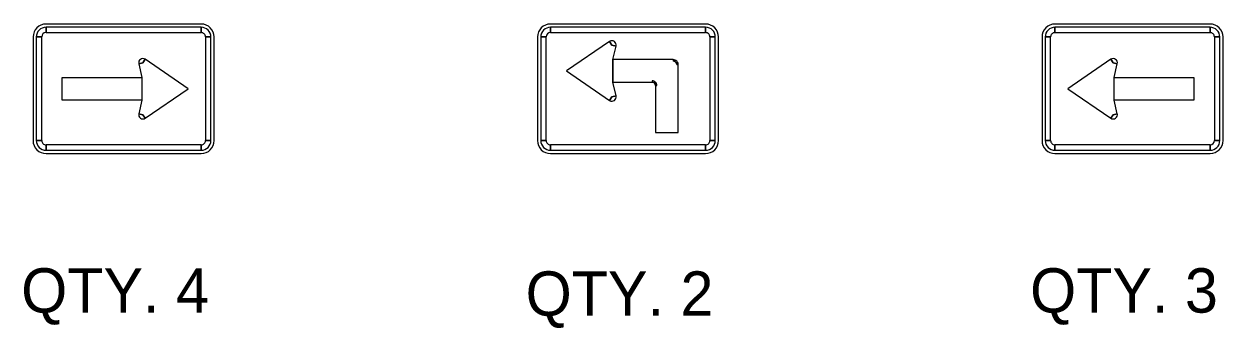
# Model space of a CAD drawing. Extents: x 10133 to 81668, y 5524 to 11018.
# Drawn here: x 25973 to 26582, y 9278 to 9432 of the extents above; entities that cross this region are included whole.
import ezdxf

# ---------------------------------------------------------------- set-up
doc = ezdxf.new("R2010")
doc.units = 0
doc.layers.add('DisCLMLSUR', color=7, linetype='Continuous')
doc.layers.add('Level 6', color=7, linetype='Continuous')

msp = doc.modelspace()

# ---------------------------------------------------------------- linework, layer by layer
at = {"layer": 'Level 6'}
for p, q in [((26063.35, 9432.44), (25984.61, 9432.44)), ((26319.35, 9432.44), (26240.61, 9432.44)), ((26575.35, 9432.44), (26496.61, 9432.44)), ((25978.05, 9425.87), (25978.05, 9373.38)), ((25979.69, 9425.87), (25982.42, 9425.87)), ((25984.61, 9428.06), (25984.61, 9430.77)), ((26063.35, 9430.77), (26063.35, 9428.06)), ((26065.54, 9425.87), (26068.27, 9425.87)), ((26069.91, 9373.38), (26069.91, 9425.87)), ((26234.05, 9425.87), (26234.05, 9373.38)), ((26235.69, 9425.87), (26238.42, 9425.87)), ((26240.61, 9428.06), (26240.61, 9430.77)), ((26319.35, 9430.77), (26319.35, 9428.06)), ((26321.54, 9425.87), (26324.27, 9425.87)), ((26325.91, 9373.38), (26325.91, 9425.87)), ((26490.05, 9425.87), (26490.05, 9373.38)), ((26491.69, 9425.87), (26494.42, 9425.87)), ((26496.61, 9428.06), (26496.61, 9430.77)), ((26575.35, 9430.77), (26575.35, 9428.06)), ((26577.54, 9425.87), (26580.27, 9425.87)), ((26581.91, 9373.38), (26581.91, 9425.87)), ((26270.61, 9423.64), (26271.78, 9421.76)), ((26271.78, 9421.76), (26273.91, 9421.28)), ((26033.82, 9412.75), (26034.99, 9414.59)), ((26302.94, 9414.41), (26302.94, 9413.67)), ((26524.97, 9414.59), (26526.14, 9412.75)), ((26031.69, 9412.27), (26033.82, 9412.75)), ((26304.69, 9411.92), (26305.41, 9411.92)), ((26526.14, 9412.75), (26528.27, 9412.27)), ((26292.28, 9403.61), (26292.28, 9402.91)), ((26293.92, 9401.29), (26294.6, 9401.29)), ((26271.78, 9395.51), (26270.61, 9393.68)), ((26273.91, 9396.04), (26271.78, 9395.51)), ((26033.82, 9386.5), (26031.69, 9386.98)), ((26034.99, 9384.66), (26033.82, 9386.5)), ((26526.14, 9386.5), (26524.97, 9384.66)), ((26528.27, 9386.98), (26526.14, 9386.5)), ((25982.42, 9373.38), (25979.69, 9373.38)), ((25984.61, 9368.48), (25984.61, 9371.19)), ((26063.35, 9371.19), (26063.35, 9368.48)), ((26068.27, 9373.38), (26065.54, 9373.38)), ((26238.42, 9373.38), (26235.69, 9373.38)), ((26240.61, 9368.46), (26240.61, 9371.19)), ((26319.35, 9371.19), (26319.35, 9368.46)), ((26324.27, 9373.38), (26321.54, 9373.38)), ((26494.42, 9373.38), (26491.69, 9373.38)), ((26496.61, 9368.48), (26496.61, 9371.19)), ((26575.35, 9371.19), (26575.35, 9368.48)), ((26580.27, 9373.38), (26577.54, 9373.38)), ((25984.61, 9366.82), (26063.35, 9366.82)), ((26240.61, 9366.82), (26319.35, 9366.82)), ((26496.61, 9366.82), (26575.35, 9366.82))]:
    msp.add_line(p, q, dxfattribs=at)
for points in [[(25979.69, 9425.87), (25979.69, 9373.38), (25982.42, 9373.38), (25982.42, 9425.87), (25979.69, 9425.87)], [(26063.35, 9430.77), (25984.61, 9430.77), (25984.61, 9428.06), (26063.35, 9428.06), (26063.35, 9430.77)], [(26068.27, 9373.38), (26068.27, 9425.87), (26065.54, 9425.87), (26065.54, 9373.38), (26068.27, 9373.38)], [(26235.69, 9425.87), (26235.69, 9373.38), (26238.42, 9373.38), (26238.42, 9425.87), (26235.69, 9425.87)], [(26319.35, 9430.77), (26240.61, 9430.77), (26240.61, 9428.06), (26319.35, 9428.06), (26319.35, 9430.77)], [(26324.27, 9373.38), (26324.27, 9425.87), (26321.54, 9425.87), (26321.54, 9373.38), (26324.27, 9373.38)], [(26491.69, 9425.87), (26491.69, 9373.38), (26494.42, 9373.38), (26494.42, 9425.87), (26491.69, 9425.87)], [(26575.35, 9430.77), (26496.61, 9430.77), (26496.61, 9428.06), (26575.35, 9428.06), (26575.35, 9430.77)], [(26580.27, 9373.38), (26580.27, 9425.87), (26577.54, 9425.87), (26577.54, 9373.38), (26580.27, 9373.38)], [(26248.81, 9408.64), (26270.61, 9393.68), (26271.78, 9395.51), (26273.91, 9396.04), (26272.32, 9402.91), (26272.32, 9414.41), (26273.91, 9421.28), (26271.78, 9421.76), (26270.61, 9423.64), (26248.81, 9408.64)], [(26056.79, 9399.63), (26034.99, 9414.59), (26033.82, 9412.75), (26031.69, 9412.27), (26033.27, 9405.36), (26033.27, 9393.9), (26031.69, 9386.98), (26033.82, 9386.5), (26034.99, 9384.66), (26056.79, 9399.63)], [(26293.92, 9377.49), (26305.41, 9377.49), (26305.41, 9411.92), (26302.94, 9414.41), (26272.32, 9414.41), (26272.32, 9402.91), (26292.28, 9402.91), (26293.92, 9402.91), (26293.92, 9401.29), (26293.92, 9377.49)], [(26503.17, 9399.63), (26524.97, 9384.66), (26526.14, 9386.5), (26528.27, 9386.98), (26526.68, 9393.9), (26526.68, 9405.36), (26528.27, 9412.27), (26526.14, 9412.75), (26524.97, 9414.59), (26503.17, 9399.63)], [(25992.81, 9393.9), (25992.81, 9405.36), (26033.27, 9405.36), (26033.27, 9393.9), (25992.81, 9393.9)], [(26567.15, 9405.36), (26567.15, 9393.9), (26526.68, 9393.9), (26526.68, 9405.36), (26567.15, 9405.36)], [(25984.61, 9368.48), (26063.35, 9368.48), (26063.35, 9371.19), (25984.61, 9371.19), (25984.61, 9368.48)], [(26240.61, 9368.46), (26319.35, 9368.46), (26319.35, 9371.19), (26240.61, 9371.19), (26240.61, 9368.46)], [(26496.61, 9368.48), (26575.35, 9368.48), (26575.35, 9371.19), (26496.61, 9371.19), (26496.61, 9368.48)]]:
    msp.add_lwpolyline(points, close=True, dxfattribs=at)
for centre, radius, start, end in [((25984.61, 9425.87), 6.56, 90.00021, 179.99985), ((26063.35, 9425.87), 6.56, 0, 90.00021), ((26240.61, 9425.87), 6.56, 90.00021, 179.99985), ((26319.35, 9425.87), 6.56, 0, 90.00021), ((26496.61, 9425.87), 6.56, 90.00006, 180.00027), ((26575.35, 9425.87), 6.56, 359.99985, 90.00006), ((25984.61, 9425.87), 4.92, 90.00021, 179.99985), ((25984.61, 9425.87), 2.19, 90.00021, 179.99985), ((26063.35, 9425.87), 4.92, 0, 90.00021), ((26063.35, 9425.87), 2.19, 0, 90.00021), ((26240.61, 9425.87), 4.92, 90.00021, 179.99985), ((26240.61, 9425.87), 2.19, 90.00021, 179.99985), ((26319.35, 9425.87), 4.92, 0, 90.00021), ((26319.35, 9425.87), 2.19, 0, 90.00021), ((26496.61, 9425.87), 4.92, 90.00006, 180.00027), ((26496.61, 9425.87), 2.19, 90.00006, 180.00027), ((26575.35, 9425.87), 4.92, 359.99985, 90.00006), ((26575.35, 9425.87), 2.19, 359.99985, 90.00006), ((26271.78, 9421.76), 2.19, 347.0497, 122.27576), ((26033.82, 9412.75), 2.19, 57.72435, 192.95041), ((26302.94, 9411.92), 2.46, 0, 90.00021), ((26302.94, 9411.92), 1.74, 0, 90.00021), ((26526.14, 9412.75), 2.19, 347.04986, 122.27592), ((26292.28, 9401.29), 2.32, 0, 90.00021), ((26292.28, 9401.29), 1.64, 0, 90.00021), ((26271.78, 9395.51), 2.19, 237.7242, 12.95026), ((26033.82, 9386.5), 2.19, 167.04986, 302.27592), ((26526.14, 9386.5), 2.19, 237.72435, 12.95041), ((25984.61, 9373.38), 6.56, 179.99985, 270.00006), ((25984.61, 9373.38), 4.92, 179.99985, 270.00006), ((25984.61, 9373.38), 2.19, 179.99985, 270.00006), ((26063.35, 9373.38), 6.56, 270.00006, 0.00027), ((26063.35, 9373.38), 4.92, 270.00006, 0.00027), ((26063.35, 9373.38), 2.19, 270.00006, 0.00027), ((26240.61, 9373.38), 6.56, 179.99985, 270.00006), ((26240.61, 9373.38), 4.92, 179.99985, 270.00006), ((26240.61, 9373.38), 2.19, 179.99985, 270.00006), ((26319.35, 9373.38), 6.56, 270.00006, 0.00027), ((26319.35, 9373.38), 4.92, 270.00006, 0.00027), ((26319.35, 9373.38), 2.19, 270.00006, 0.00027), ((26496.61, 9373.38), 6.56, 180, 270.00021), ((26496.61, 9373.38), 4.92, 180, 270.00021), ((26496.61, 9373.38), 2.19, 180, 270.00021), ((26575.35, 9373.38), 6.56, 270.00021, 359.99985), ((26575.35, 9373.38), 4.92, 270.00021, 359.99985), ((26575.35, 9373.38), 2.19, 270.00021, 359.99985)]:
    msp.add_arc(centre, radius, start, end, dxfattribs=at)

# ---------------------------------------------------------------- texts
at = {"layer": 'DisCLMLSUR'}
for s, p in [('QTY. 4', (25972.01, 9286.19)), ('QTY. 2', (26228.01, 9284.6)), ('QTY. 3', (26484.01, 9286.19))]:
    msp.add_text(s, height=22.5, dxfattribs=at).set_placement(p)

doc.saveas('drawing.dxf')
